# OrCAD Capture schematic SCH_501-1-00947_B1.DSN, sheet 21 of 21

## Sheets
21 P15_BOOT/UART HEADER: size A2
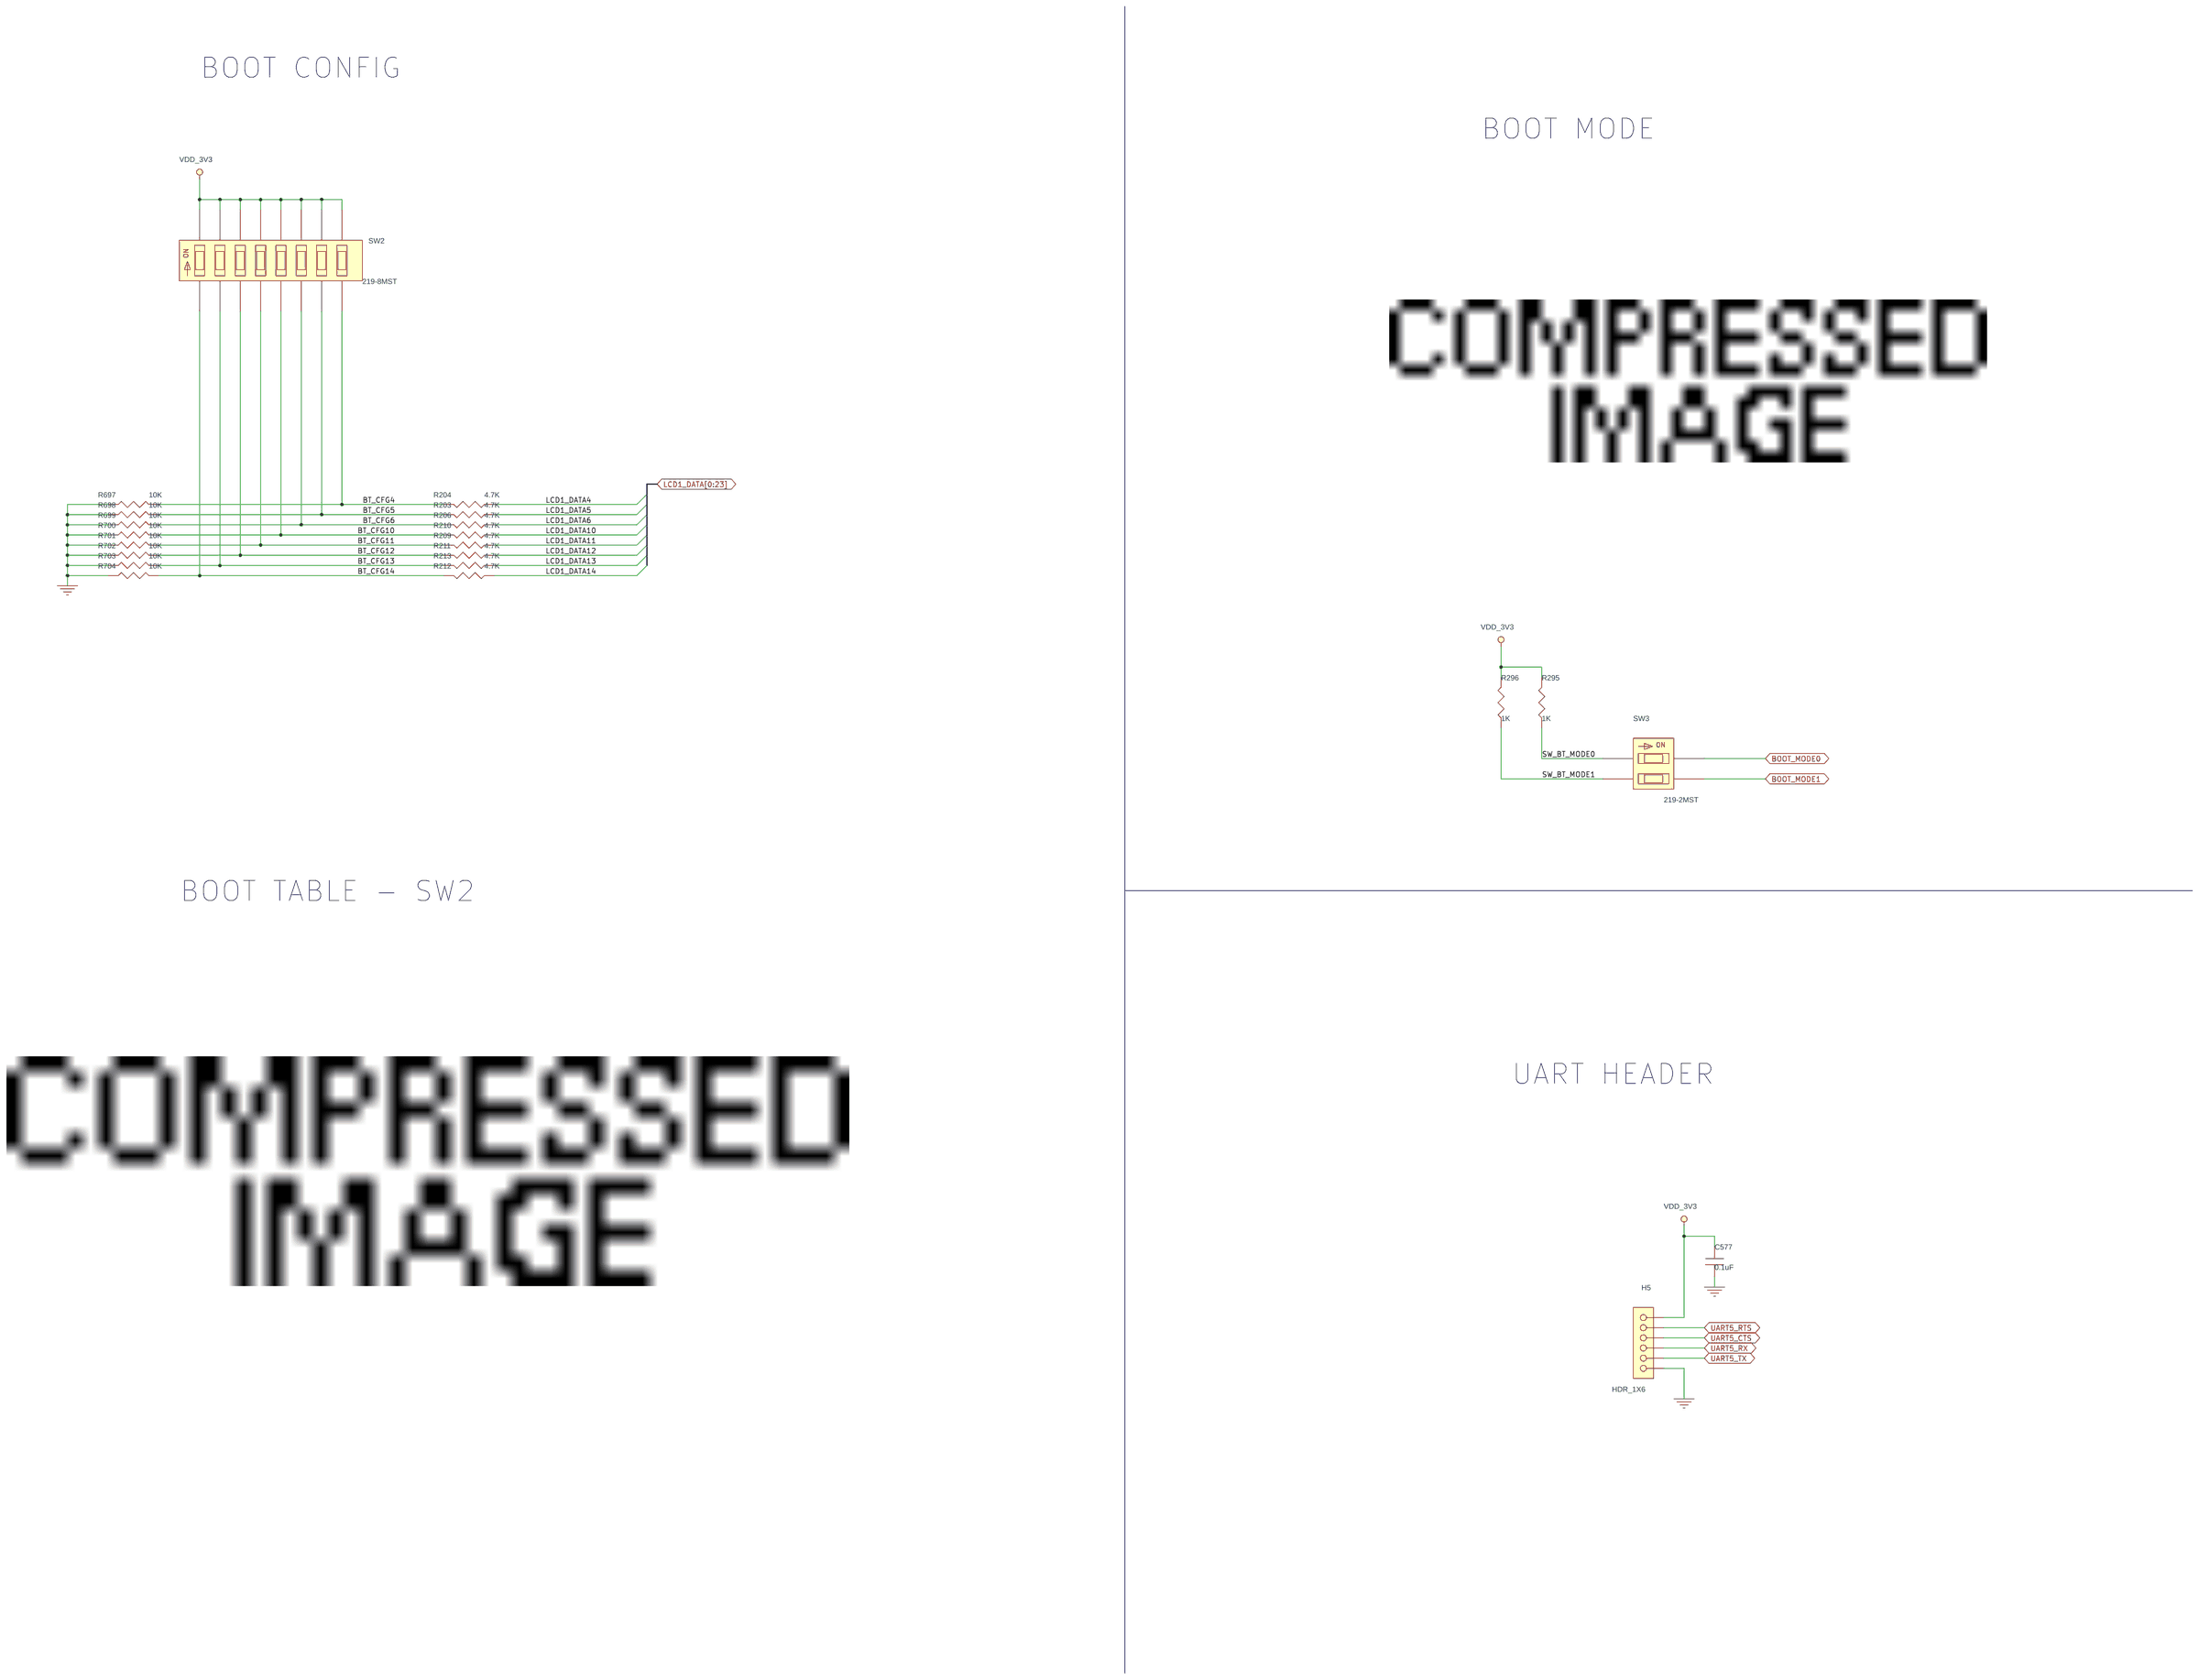
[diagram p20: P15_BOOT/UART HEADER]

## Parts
C577  0.1uF  [C0402]
H5  HDR_1X6  [CON_BERG_6M_2P54_TH]
R203  4.7K  [R0402]
R204  4.7K  [R0402]
R206  4.7K  [R0402]
R209  4.7K  [R0402]
R210  4.7K  [R0402]
R211  4.7K  [R0402]
R212  4.7K  [R0402]
R213  4.7K  [R0402]
R295  1K  [R0402]
R296  1K  [R0402]
R697  10K  [R0402]
R698  10K  [R0402]
R699  10K  [R0402]
R700  10K  [R0402]
R701  10K  [R0402]
R702  10K  [R0402]
R703  10K  [R0402]
R704  10K  [R0402]
SW2  219-8MST  [SW16_2P54_21P79X6P7_A1]
SW3  219-2MST  [SW4_2P54_6P95X6P55]

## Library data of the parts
C577 = CAP_NP: Cap, Cer-X7R, 0.1uF, 16V, 10%, 0402; EN: 102-1-01629; KEY Number: 102-1-01629@4; Mfg: MURATA MANUFACTURING CO,LTD; Mfg Part No: GRM155R71C104KA88*; Temperature: -55°C to +125°C
H5 = HDR_1X6_6P: Conn, Berg strip, 1x6, 2.54mm, 3A, ST, TH; EN: 201-1-00063; KEY Number: 201-1-00063@1; Mfg: SAMTEC INC; Mfg Part No: TSW-106-14-G-S
R203 R204 R206 R209-R213 = RES: Res, Chip, 4.7K, 1/16W, 1%, 0402; EN: 101-1-03446; KEY Number: 101-1-03446@2; Mfg: WALSIN TECHNOLOGY CORP.; Mfg Part No: WR04X4701FTL; Temperature: -55°C to +155°C
R295 R296 = RES: Res, Chip, 1K, 1/16W, 5%, 0402; EN: 101-1-02769; KEY Number: 101-1-02769@4; Mfg: WALSIN TECHNOLOGY CORP.; Mfg Part No: WR04X102JTL; Temperature: -55°C to +155°C
R697-R704 = RES: Res, Chip, 10K, 1/16W, 5%, 0402; EN: 101-1-02793; KEY Number: 101-1-02793@2; Mfg: VISHAY; Mfg Part No: CRCW040210K0JNED; Temperature: -55°C to +155°C
SW2 = SWITCH_DIPX8_16P_B: Switch, DIP, 8 Position, SPST, 100mA, 20V, Vertical, SMD; EN: 205-1-00159; KEY Number: 205-1-00159@1; Mfg: CTS; Mfg Part No: 219-8MST*; Temperature: -55°C to +85°C
SW3 = SWITCH_DIPX2_4P_B: Switch, DIP, 2 Position, 0.1A, Vertical,  SMD; EN: 205-1-00027; KEY Number: 205-1-00027@1; Mfg: CTS

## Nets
GND: C577.2 H5.6 R697.1 R698.1 R699.1 R700.1 R701.1 R702.1 R703.1 R704.1 ; also on sheet 1 4 5 6 7 8 9 10 11 13 14 15 16 17 18 19 20
VDD_3V3: C577.1 H5.1 R295.2 R296.2 SW2.9 SW2.10 SW2.11 SW2.12 SW2.13 SW2.14 SW2.15 SW2.16 ; also on sheet 1 5 6 7 8 11 12 13 15 16 17 18 19 20
BOOT_MODE0: SW3.4 ; also on sheet 7
BOOT_MODE1: SW3.3 ; also on sheet 7
BT_CFG4: R204.2 R697.2 SW2.8
BT_CFG5: R203.2 R698.2 SW2.7
BT_CFG6: R206.2 R699.2 SW2.6
BT_CFG10: R210.2 R700.2 SW2.5
BT_CFG11: R209.2 R701.2 SW2.4
BT_CFG12: R211.2 R702.2 SW2.3
BT_CFG13: R213.2 R703.2 SW2.2
BT_CFG14: R212.2 R704.2 SW2.1
LCD1_DATA4: R204.1 ; also on sheet 7 17
LCD1_DATA5: R203.1 ; also on sheet 7 17
LCD1_DATA6: R206.1 ; also on sheet 7 17
LCD1_DATA10: R210.1 ; also on sheet 7 17
LCD1_DATA11: R209.1 ; also on sheet 7 17
LCD1_DATA12: R211.1 ; also on sheet 7 17
LCD1_DATA13: R213.1 ; also on sheet 7 17
LCD1_DATA14: R212.1 ; also on sheet 7 17
SW_BT_MODE0: R295.1 SW3.1
SW_BT_MODE1: R296.1 SW3.2
UART5_CTS: H5.3 ; also on sheet 7
UART5_RTS: H5.2 ; also on sheet 7
UART5_RX: H5.4 ; also on sheet 8
UART5_TX: H5.5 ; also on sheet 8

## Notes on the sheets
sheet 21
- BOOT CONFIG
- BOOT MODE
- BOOT TABLE - SW2
- UART HEADER
